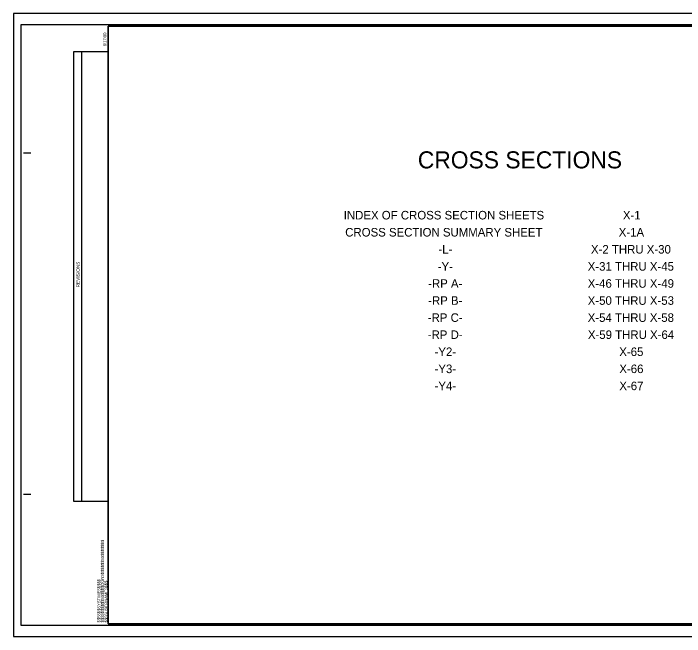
# Model space of a CAD drawing. Extents: x 2862872 to 2864765, y 971793 to 972888.
# Drawn here: x 2862872 to 2864051, y 971793 to 972888 of the extents above; entities that cross this region are included whole.
import ezdxf

# ---------------------------------------------------------------- set-up
doc = ezdxf.new("R2010")
doc.units = 0
for name, color, linetype in [('Sheet Block Revision CELL', 7, 'Continuous'), ('Sheet Cutting Line CELL', 7, 'Continuous'), ('Sheet Plan CELL', 7, 'Continuous'), ('Sheet Plot Border Inside CELL', 7, 'Continuous'), ('Sheet Plot Border Outside CELL', 7, 'Continuous'), ('Sheet XS Number', 7, 'Continuous')]:
    doc.layers.add(name, color=color, linetype=linetype)

msp = doc.modelspace()

# ---------------------------------------------------------------- linework, layer by layer
at = {"layer": 'Sheet Block Revision CELL'}
msp.add_line((2862992.6, 972030.8), (2862992.6, 972821.5), dxfattribs=at)
msp.add_line((2862992.6, 972030.8), (2862992.6, 972821.5), dxfattribs=at)
msp.add_lwpolyline([(2862978.1, 972030.8), (2862978.1, 972821.5), (2863038.6, 972821.5), (2863038.6, 972030.8)], close=True, dxfattribs=at)
msp.add_lwpolyline([(2862978.1, 972030.8), (2862978.1, 972821.5), (2863038.6, 972821.5), (2863038.6, 972030.8)], close=True, dxfattribs=at)
at = {"layer": 'Sheet Cutting Line CELL'}
for p, q in [((2864555.6, 972888.3), (2862872.1, 972888.3)), ((2862872.1, 972888.3), (2862872.1, 971793.3)), ((2862872.1, 971793.3), (2864555.6, 971793.3))]:
    msp.add_line(p, q, dxfattribs=at)
at = {"layer": 'Sheet Plan CELL'}
for p, q in [((2863038.6, 972865.8), (2863038.6, 972865.8)), ((2863038.6, 972865.8), (2863038.6, 972865.8)), ((2862890.1, 972643.3), (2862902.6, 972643.3)), ((2862890.1, 972643.3), (2862902.6, 972643.3)), ((2862890.1, 972043.3), (2862902.6, 972043.3)), ((2862890.1, 972043.3), (2862902.6, 972043.3)), ((2863038.6, 971815.8), (2863038.6, 971815.8)), ((2863038.6, 971815.8), (2863038.6, 971815.8))]:
    msp.add_line(p, q, dxfattribs=at)
for points in [[(2864538.7, 972865.8), (2863038.6, 972865.8), (2863038.6, 971815.8), (2864538.6, 971815.8)], [(2863038.6, 971815.8), (2863038.6, 972865.8), (2864338.6, 972865.8), (2864338.6, 972715.8), (2864538.6, 972715.8), (2864538.6, 971815.8)], [(2864538.7, 972865.8), (2863038.6, 972865.8), (2863038.6, 971815.8), (2864538.6, 971815.8)], [(2863038.6, 971815.8), (2863038.6, 972865.8), (2864338.6, 972865.8), (2864338.6, 972715.8), (2864538.6, 972715.8), (2864538.6, 971815.8)]]:
    msp.add_lwpolyline(points, close=True, dxfattribs=at)
at = {"layer": 'Sheet Plot Border Inside CELL'}
msp.add_lwpolyline([(2862885.1, 971813.3), (2864551.1, 971813.3), (2864551.1, 972868.3), (2862885.1, 972868.3)], close=True, dxfattribs=at)
at = {"layer": 'Sheet Plot Border Outside CELL'}
msp.add_lwpolyline([(2862872.1, 971793.3), (2864555.6, 971793.3), (2864555.6, 972888.3), (2862872.1, 972888.3)], close=True, dxfattribs=at)
msp.add_lwpolyline([(2862872.1, 971793.3), (2864555.6, 971793.3), (2864555.6, 972888.3), (2862872.1, 972888.3)], close=True, dxfattribs=at)

# ---------------------------------------------------------------- texts
at = {"layer": 'Sheet Block Revision CELL'}
msp.add_text('REVISIONS', height=6, rotation=90, dxfattribs=at).set_placement((2862988.6, 972407))
msp.add_text('REVISIONS', height=6, rotation=90, dxfattribs=at).set_placement((2862988.6, 972407))
at = {"layer": 'Sheet Plan CELL'}
for s, p in [('8/17/99', (2863035.4, 972830.6)), ('8/17/99', (2863035.4, 972830.6)), ('$$$$$$$$$$$$$$$$DGN$$$$$$$$$$$$$$$$', (2863031, 971818.2)), ('$$$$$$$$$$$$$$$$DGN$$$$$$$$$$$$$$$$', (2863031, 971818.2)), ('$$$$$$SYSTIME$$$$$', (2863024.9, 971818.2)), ('$$$$$$SYSTIME$$$$$', (2863024.9, 971818.2)), ('$$$$USERNAME$$$$', (2863037.5, 971818.2)), ('$$$$USERNAME$$$$', (2863037.5, 971818.2))]:
    msp.add_text(s, height=5.25, rotation=90, dxfattribs=at).set_placement(p)
at = {"layer": 'Sheet XS Number'}
for s, height, p in [('CROSS SECTIONS', 30, (2863582.7, 972616)), ('INDEX OF CROSS SECTION SHEETS', 15, (2863452.5, 972526.3)), ('X-1', 15, (2863943, 972526.3)), ('CROSS SECTION SUMMARY SHEET', 15, (2863455.1, 972496.3)), ('X-1A', 15, (2863935.7, 972496.3)), ('-L-', 15, (2863618.9, 972466.3)), ('X-2 THRU X-30', 15, (2863886.9, 972466.3)), ('-Y-', 15, (2863617.7, 972436.3)), ('X-31 THRU X-45', 15, (2863881.2, 972436.3)), ('-RP A-', 15, (2863600.8, 972406.3)), ('X-46 THRU X-49', 15, (2863881.2, 972406.3)), ('-RP B-', 15, (2863600.8, 972376.3)), ('X-50 THRU X-53', 15, (2863881.2, 972376.3)), ('-RP C-', 15, (2863600.2, 972346.3)), ('X-54 THRU X-58', 15, (2863881.2, 972346.3)), ('-RP D-', 15, (2863600.2, 972316.3)), ('X-59 THRU X-64', 15, (2863881.5, 972316.3)), ('-Y2-', 15, (2863612.1, 972286.3)), ('X-65', 15, (2863936.7, 972286.3)), ('-Y3-', 15, (2863612.1, 972256.3)), ('X-66', 15, (2863936.8, 972256.3)), ('-Y4-', 15, (2863612.1, 972226.3)), ('X-67', 15, (2863936.8, 972226.3))]:
    msp.add_text(s, height=height, dxfattribs=at).set_placement(p)

doc.saveas('drawing.dxf')
